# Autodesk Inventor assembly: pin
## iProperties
Created: 2007-01
Part Number: pin
Cost Center: 0 kg
Document SubType Name: Assembly
Designer: M. Fiedler
SaveDate: 2007-01-25
SaveTime: 21:26
FileName: pin
Masse: 0 kg
Author: M. Fiedler
